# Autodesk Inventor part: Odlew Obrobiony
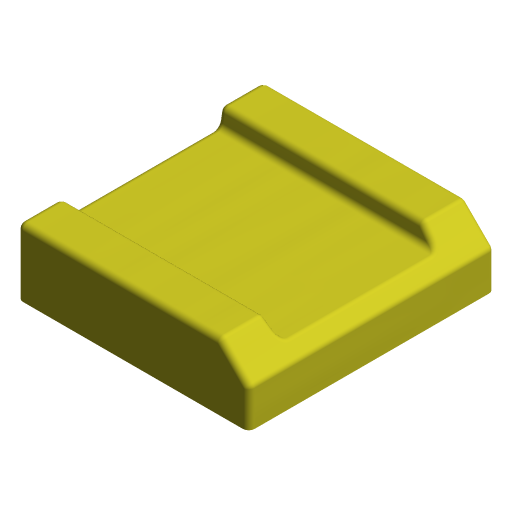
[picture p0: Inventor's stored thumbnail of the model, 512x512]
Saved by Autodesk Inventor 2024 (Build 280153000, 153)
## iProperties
Company: ATC
Shininess: 20.0
Length Units: 11269
Angle Units: 11279
Time Units: 11290
Mass Units: 11283
Length Display Precision: 3
Angle Display Precision: 2
Compacted: True
Created: 2023-03
Part Number: Odlew Obrobiony
Document SubType Name: Modeling
Designer: Andrzej Jaskulski
Material: Kurs-AJ
Density: 1 g/cm^3
Appearance: Kanarkowa
Checked By: A.J.
Engr Approved By: Andrzej Jaskulski
Mfg Approved By: Andrzej Jaskulski
Authority: A.J.
Density: 0.0
Volumn: 0.0
Area: 0.0
PropertySet Name: Model Information
Control State: 0
Master: False
Checked Out: False
Title: A.J.: Kurs R2024-MEP
Author: Andrzej Jaskulski
Revision Number: 1/24
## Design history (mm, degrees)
node "Płyta" dims "d0" = 0, "d1" = 23 (= WYSOKOŚĆ + NADDATEK)
  sketch "Sketch2"
    geometry: L1 (-65, -5)-(20, -5); L2 (20, -5)-(20, 75) reference; L3 (20, 75)-(-65, 75) reference; L4 (-65, 75)-(-65, -5)
    constraints: 8 end point, 2 parallel, 1 horizontal, 1 perpendicular, 1 vertical
    dimensions: "d3" = 85 distance of L1.start L1.end (= SZEROKOŚĆ); "d2" = 80 distance of L1.end L2.end (= GŁĘBOKOŚĆ)
node "Chamfer1" dims "d4" = 10, "d5" = 10, "d30" = 45 deg
node "Wybranie" dims "d6" = 0, "d7" = 10
  sketch "Sketch3"
    geometry: L1 (0, -23)-(85, -23) reference; L2 (85, 0)-(0, 0) reference; L3 (15, -23)-(16.058, -17); L4 (16.058, -17)-(68.942, -17); L5 (68.942, -17)-(70, -23); L6 (42.5, -17)-(42.5, -23)
    constraints: 8 end point, 2 midpoint, 2 point on line, 1 equal length, 1 parallel, 1 vertical
    dimensions: "d9" = 6 distance between parallel lines of L1 L4 (= 2 x NADDATEK); "d8" = 100 deg angle of L4 L3; "d10" = 15 distance of L3.start L1.start; "d23" = 15 distance of L5.end L1.end
fillet "Fillet2" dims "d29" = 2 (= PROMIEŃ)
node "Bryła1"
node "Korpusy bryłowe"
node "Korpusy powierzchniowe"
other parameters: "d27" = 8.5, "SZEROKOŚĆ" = 85 [user parameter; used in 1 equation term], "GŁĘBOKOŚĆ" = 80 [user parameter; used in 1 equation term], "NADDATEK" = 3 [user parameter; used in 2 equation terms], "PROMIEŃ" = 2 [user parameter; used in 1 equation term]
